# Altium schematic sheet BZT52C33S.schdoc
size 127 x 101 mm
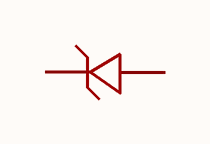
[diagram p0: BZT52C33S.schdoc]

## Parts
D?  bzt52c33s_c22637  [SOD-323_L1.8-W1.3-LS2.5-RD]  (value not drawn)

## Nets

Not connected (* = marked no-connect by the designer): D? 1(K) 2(A)

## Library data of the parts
D? = bzt52c33s_c22637: 二极管配置:1个独立式;稳压值(标称值):33V;稳压值(范围值):31V~35V;耗散功率(Pd):200mW;; Manufacturer: CJ(江苏长电/长晶); AddInBom: yes; ModelId: db63db13d9e342eb939127d413d6200b; ModelTransform: 104.3305,51.181,0,0,0,0,0,-0.004,0; Diode Configuration: 1个独立式; Zener Voltage(Nom): 33V; Reverse Leakage Current (Ir): 100nA; Pd - Power Dissipation: 200mW; Impedance(Zzt): 80Ω; Impedance(Zzk): 325Ω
